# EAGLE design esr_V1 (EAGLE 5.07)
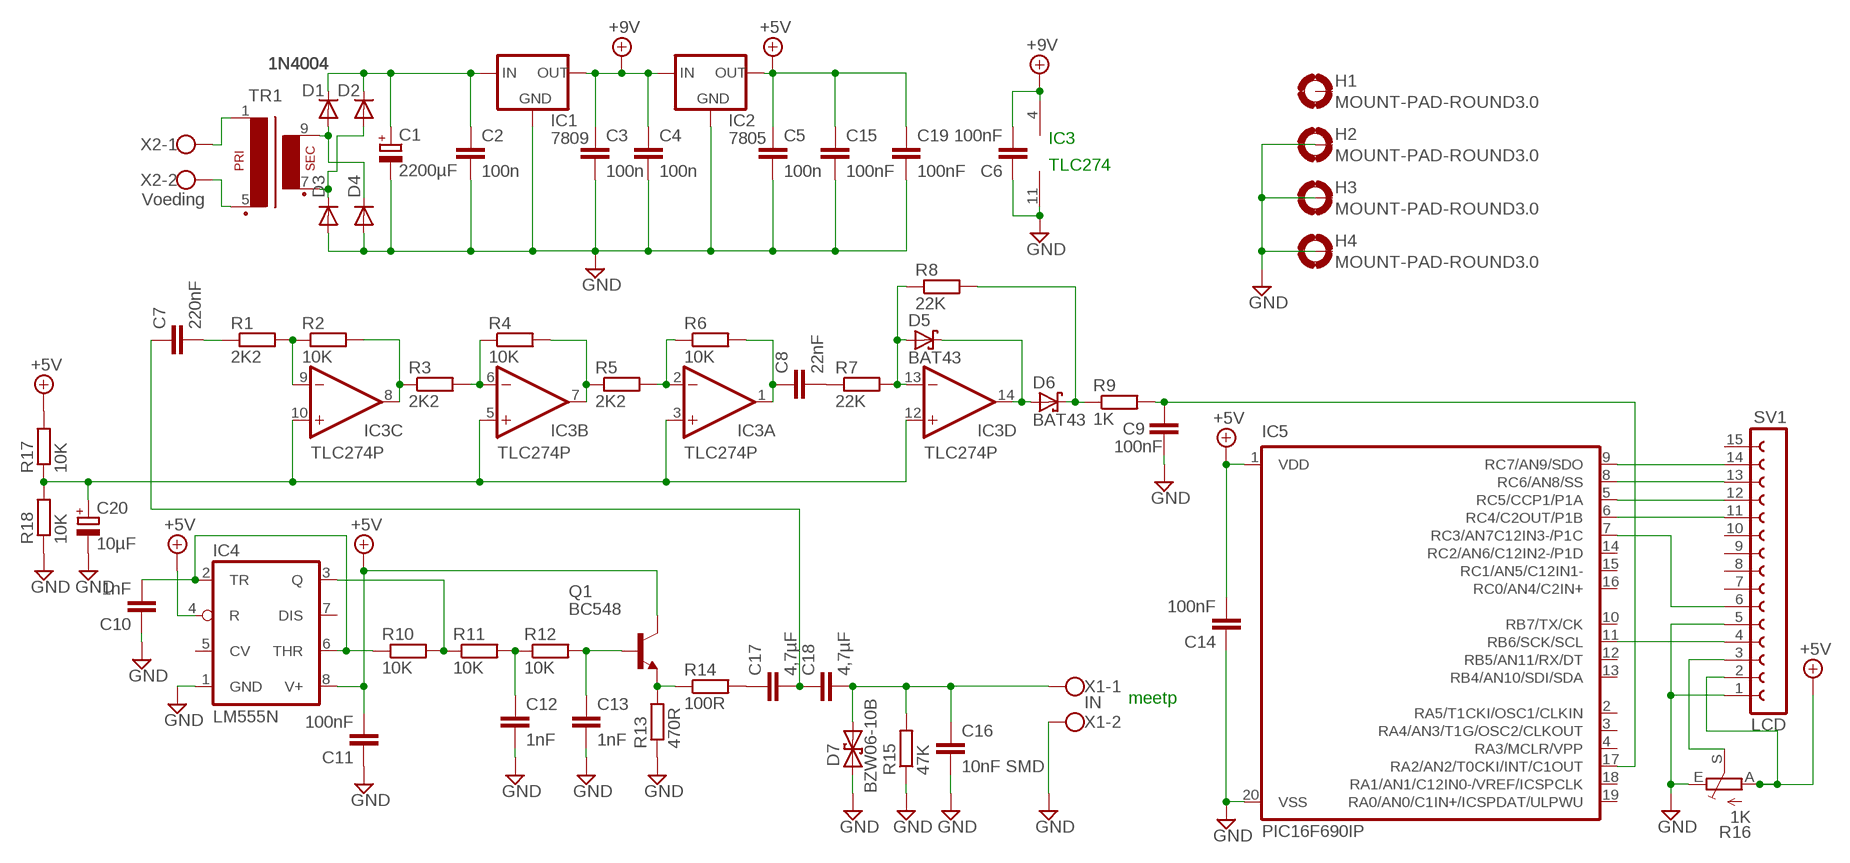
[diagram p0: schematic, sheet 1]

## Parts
C1  2200µF  CPOL-EUE7.5-18  [E7,5-18]
C2  100n  C-EU050-025X075  [C050-025X075]
C3  100n  C-EU050-025X075  [C050-025X075]
C4  100n  C-EU050-025X075  [C050-025X075]
C5  100n  C-EU050-025X075  [C050-025X075]
C6  100nF  C-EU050-025X075  [C050-025X075]
C7  220nF  C-EU050-025X075  [C050-025X075]
C8  22nF  C-EU050-025X075  [C050-025X075]
C9  100nF  C-EU050-025X075  [C050-025X075]
C10  1nF  C-EU050-025X075  [C050-025X075]
C11  100nF  C-EU050-025X075  [C050-025X075]
C12  1nF  C-EU050-025X075  [C050-025X075]
C13  1nF  C-EU050-025X075  [C050-025X075]
C14  100nF  C-EU050-025X075  [C050-025X075]
C15  100nF  C-EU050-025X075  [C050-025X075]
C16  10nF SMD  C-EU050-025X075  [C050-025X075]
C17  4,7µF  C-EU275-113X316  [C275-113X316]
C18  4,7µF  C-EU275-113X316  [C275-113X316]
C19  100nF  C-EU050-025X075  [C050-025X075]
C20  10µF  CPOL-EUE5-8.5  [E5-8,5]
D1  1N4004  [DO41-10]
D2  1N4004  [DO41-10]
D3  1N4004  [DO41-10]
D4  1N4004  [DO41-10]
D5  BAT43  BAT42  [DO35-10]
D6  BAT43  BAT42  [DO35-10]
D7  BZW06-10B  BZW04XXB  [F126Z12]
H1  MOUNT-PAD-ROUND3.0  [3,0-PAD]
H2  MOUNT-PAD-ROUND3.0  [3,0-PAD]
H3  MOUNT-PAD-ROUND3.0  [3,0-PAD]
H4  MOUNT-PAD-ROUND3.0  [3,0-PAD]
IC1  7809  78XXS  [78XXS]
IC2  7805  78XXS  [78XXS]
IC3  TLC274P  [DIL14]
IC4  LM555N  [DIL08]
IC5  PIC16F690IP  [DIL20]
Q1  BC548  [TO92-EBC]
R1  2K2  R-EU_0204/7  [0204/7]
R2  10K  R-EU_0204/7  [0204/7]
R3  2K2  R-EU_0204/7  [0204/7]
R4  10K  R-EU_0204/7  [0204/7]
R5  2K2  R-EU_0204/7  [0204/7]
R6  10K  R-EU_0204/7  [0204/7]
R7  22K  R-EU_0204/7  [0204/7]
R8  22K  R-EU_0204/7  [0204/7]
R9  1K  R-EU_0204/7  [0204/7]
R10  10K  R-EU_0204/7  [0204/7]
R11  10K  R-EU_0204/7  [0204/7]
R12  10K  R-EU_0204/7  [0204/7]
R13  470R  R-EU_0204/7  [0204/7]
R14  100R  R-EU_0204/7  [0204/7]
R15  47K  R-EU_0204/7  [0204/7]
R16  1K  TRIM_EU-S63P  [S63P]
R17  10K  R-EU_0204/7  [0204/7]
R18  10K  R-EU_0204/7  [0204/7]
SV1  LCD  FE15-1  [FE15]
TR1  EI30-1  [EI30-1]
X1  IN  W237-102  [W237-102]
X2  Voeding  W237-2N  [W237-2N]

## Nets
+5V: C5.1 C11.2 C14.2 C15.1 C19.1 IC2.OUT IC4.4(R) IC4.8(V+) IC5.1(VDD) Q1.C R16.A R17.2 SV1.2
+9V: C3.1 C4.1 C6.2 IC1.OUT IC2.IN IC3.4(P:V+)
GND: C1.- C2.2 C3.2 C4.2 C5.2 C6.1 C9.1 C10.1 C11.1 C12.2 C13.2 C14.1 C15.2 C16.2 C19.2 C20.- D3.A D4.A D7.A H2.B3,0(MOUNT) H3.B3,0(MOUNT) H4.B3,0(MOUNT) IC1.GND IC2.GND IC3.11(P:V-) IC4.1(GND) IC5.20(VSS) R13.1 R15.1 R16.E R18.1 SV1.1 SV1.5 X1.2
N$1: TR1.5(P2) X2.2
N$2: TR1.1 X2.1
N$3: D1.A D4.C TR1.9(S4)
N$4: D2.A D3.C TR1.7(S3)
N$6: IC3.8(C:OUT) R2.2 R3.1
N$7: IC3.6(B:-IN) R3.2 R4.1
N$8: C7.2 R1.1
N$9: IC3.9(C:-IN) R1.2 R2.1
N$10: IC3.7(B:OUT) R4.2 R5.1
N$11: IC5.9(RC7/AN9/SDO) SV1.14
N$13: C8.2 R7.1
N$14: D5.A IC3.13(D:-IN) R7.2 R8.1
N$15: D5.C D6.A IC3.14(D:OUT)
N$16: D6.C R8.2 R9.1
N$17: C9.2 IC5.17(RA2/AN2/T0CKI/INT/C1OUT) R9.2
N$18: C10.2 IC4.2(TR) IC4.6(THR) R10.1
N$19: IC4.3(Q) R10.2 R11.1
N$20: C12.1 R11.2 R12.1
N$21: C13.1 Q1.B R12.2
N$22: Q1.E R13.2 R14.1
N$23: C17.1 R14.2
N$24: IC3.2(A:-IN) R5.2 R6.1
N$25: C7.1 C17.2 C18.1
N$26: C16.1 C18.2 D7.C R15.2 X1.1
N$27: IC5.8(RC6/AN8/SS) SV1.13
N$28: IC5.5(RC5/CCP1/P1A) SV1.12
N$29: IC5.6(RC4/C2OUT/P1B) SV1.11
N$30: IC5.11(RB6/SCK/SCL) SV1.4
N$31: IC5.7(RC3/AN7C12IN3-/P1C) SV1.6
N$32: C8.1 IC3.1(A:OUT) R6.2
N$35: C20.+ IC3.3(A:+IN) IC3.5(B:+IN) IC3.10(C:+IN) IC3.12(D:+IN) R17.1 R18.2
N$37: R16.S SV1.3
N$72: C1.+ C2.1 D1.C D2.C IC1.IN
Unconnected: H1.B3,0(MOUNT) IC4.5(CV) IC4.7(DIS) IC5.2(RA5/T1CKI/OSC1/CLKIN) IC5.3(RA4/AN3/T1G/OSC2/CLKOUT) IC5.4(RA3/MCLR/VPP) IC5.10(RB7/TX/CK) IC5.12(RB5/AN11/RX/DT) IC5.13(RB4/AN10/SDI/SDA) IC5.14(RC2/AN6/C12IN2-/P1D) IC5.15(RC1/AN5/C12IN1-) IC5.16(RC0/AN4/C2IN+) IC5.18(RA1/AN1/C12IN0-/VREF/ICSPCLK) IC5.19(RA0/AN0/C1IN+/ICSPDAT/ULPWU) SV1.7 SV1.8 SV1.9 SV1.10 SV1.15

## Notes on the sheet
- IC3
- TLC274
- meetp

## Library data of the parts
C1 C20 = rcl:CPOL-EU: POLARIZED CAPACITOR, European symbol
C2-C19 = rcl:C-EU: CAPACITOR, European symbol
D1-D4 = diode:1N4004: DIODE
D5 D6 = diode:BAT42: DIODE
D7 = diode:BZW04XXB: DIODE
H1-H4 = holes:MOUNT-PAD-ROUND: MOUNTING PAD, round
IC1 IC2 = v-reg:78XXS: VOLTAGE REGULATOR
IC3 = linear:TLC274: OP AMP
IC4 = linear:*555: TIMER
IC5 = microchip-5:PIC16F690*: MICROCONTROLLER PIC16F690 18 I/O One 16-bit timer Two 8-bit timer Two comparators Precision internal oscillator-software selectable 8 MHz - 32 KHz SSP w/ I2C Compatible Address mask option EUSART LIN 2.0 Compatible ECCP+ w/ PWM Steering 12 A/D Channels ULPW Enhanced Low Power Timer 1 Timer 1 Gate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
Q1 = transistor-npn:BC548*: NPN Transistor
R1-R15 R17 R18 = rcl:R-EU_: RESISTOR, European symbol
R16 = pot:TRIM_EU-: POTENTIOMETER
SV1 = con-lsta:FE15-1: FEMALE HEADER
TR1 = trafo:EI30-1: TRANSFORMER 1 primary winding, 1 secondary winding ERA
X1 = con-wago-500:W237-102: WAGO SCREW CLAMP
X2 = con-wago-508:W237-2N: WAGO SREW CLAMP

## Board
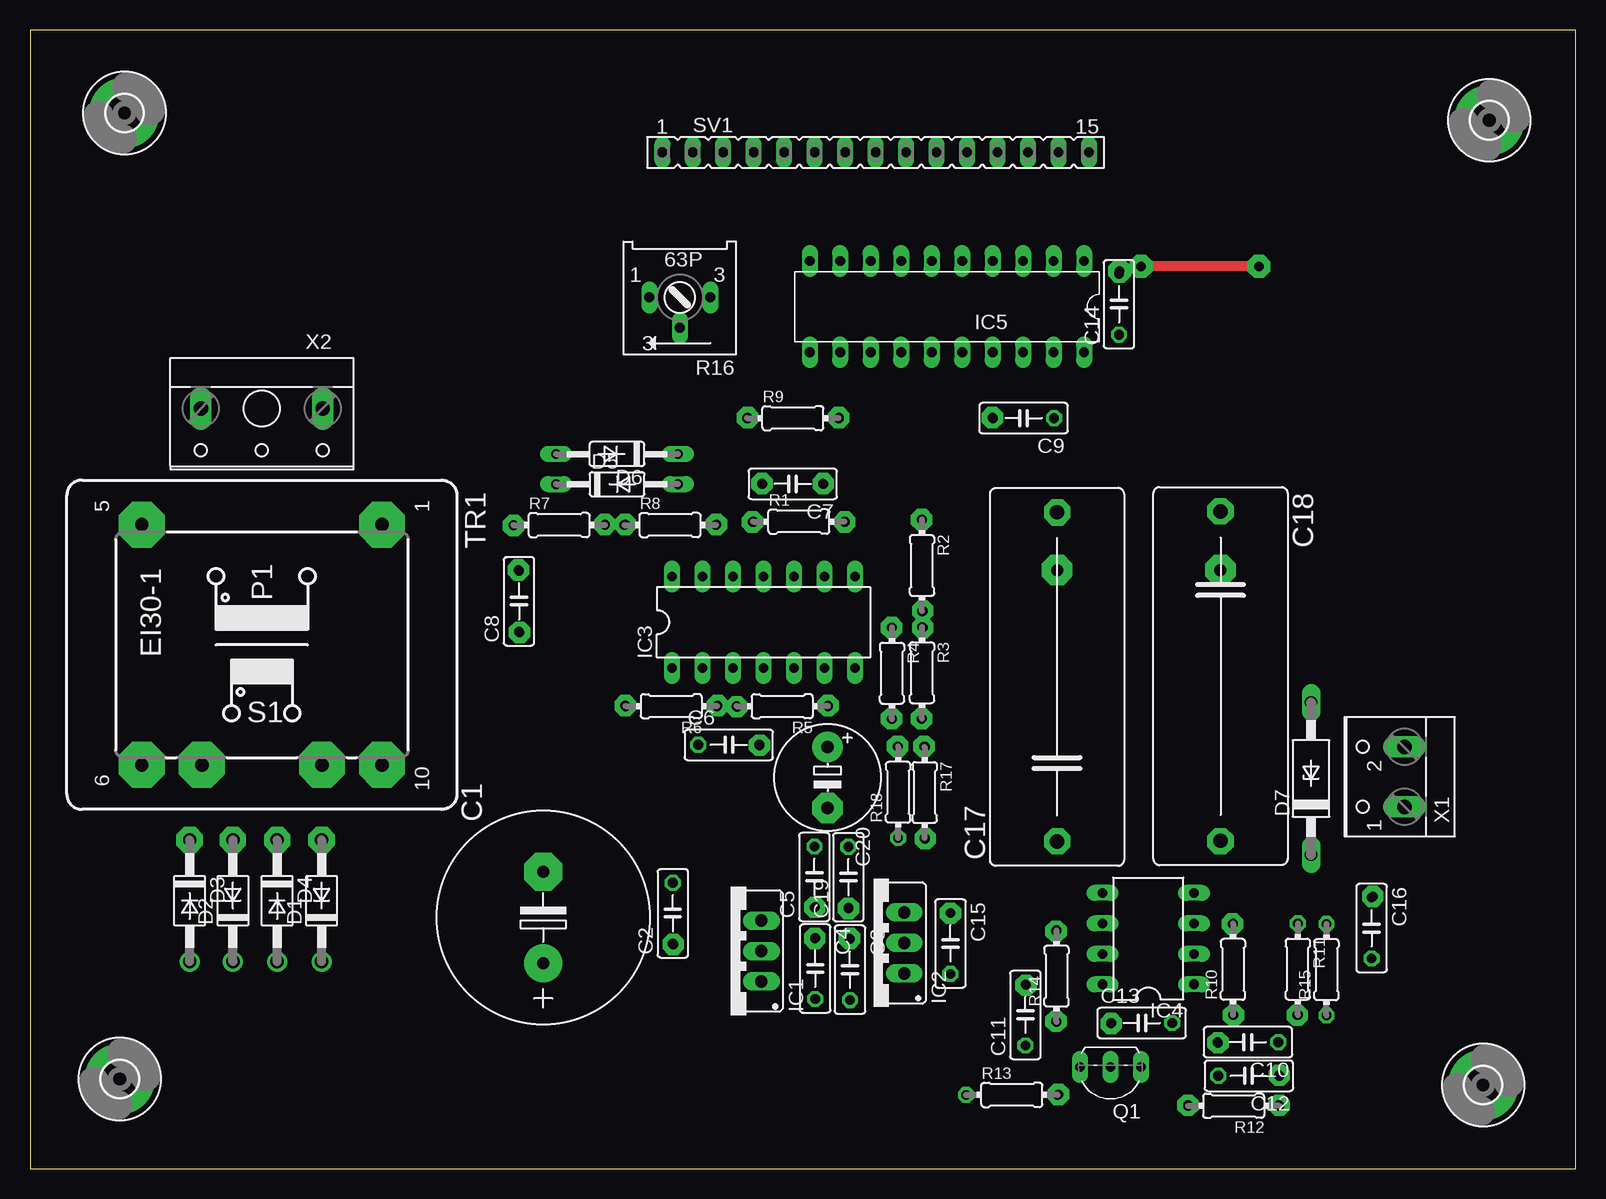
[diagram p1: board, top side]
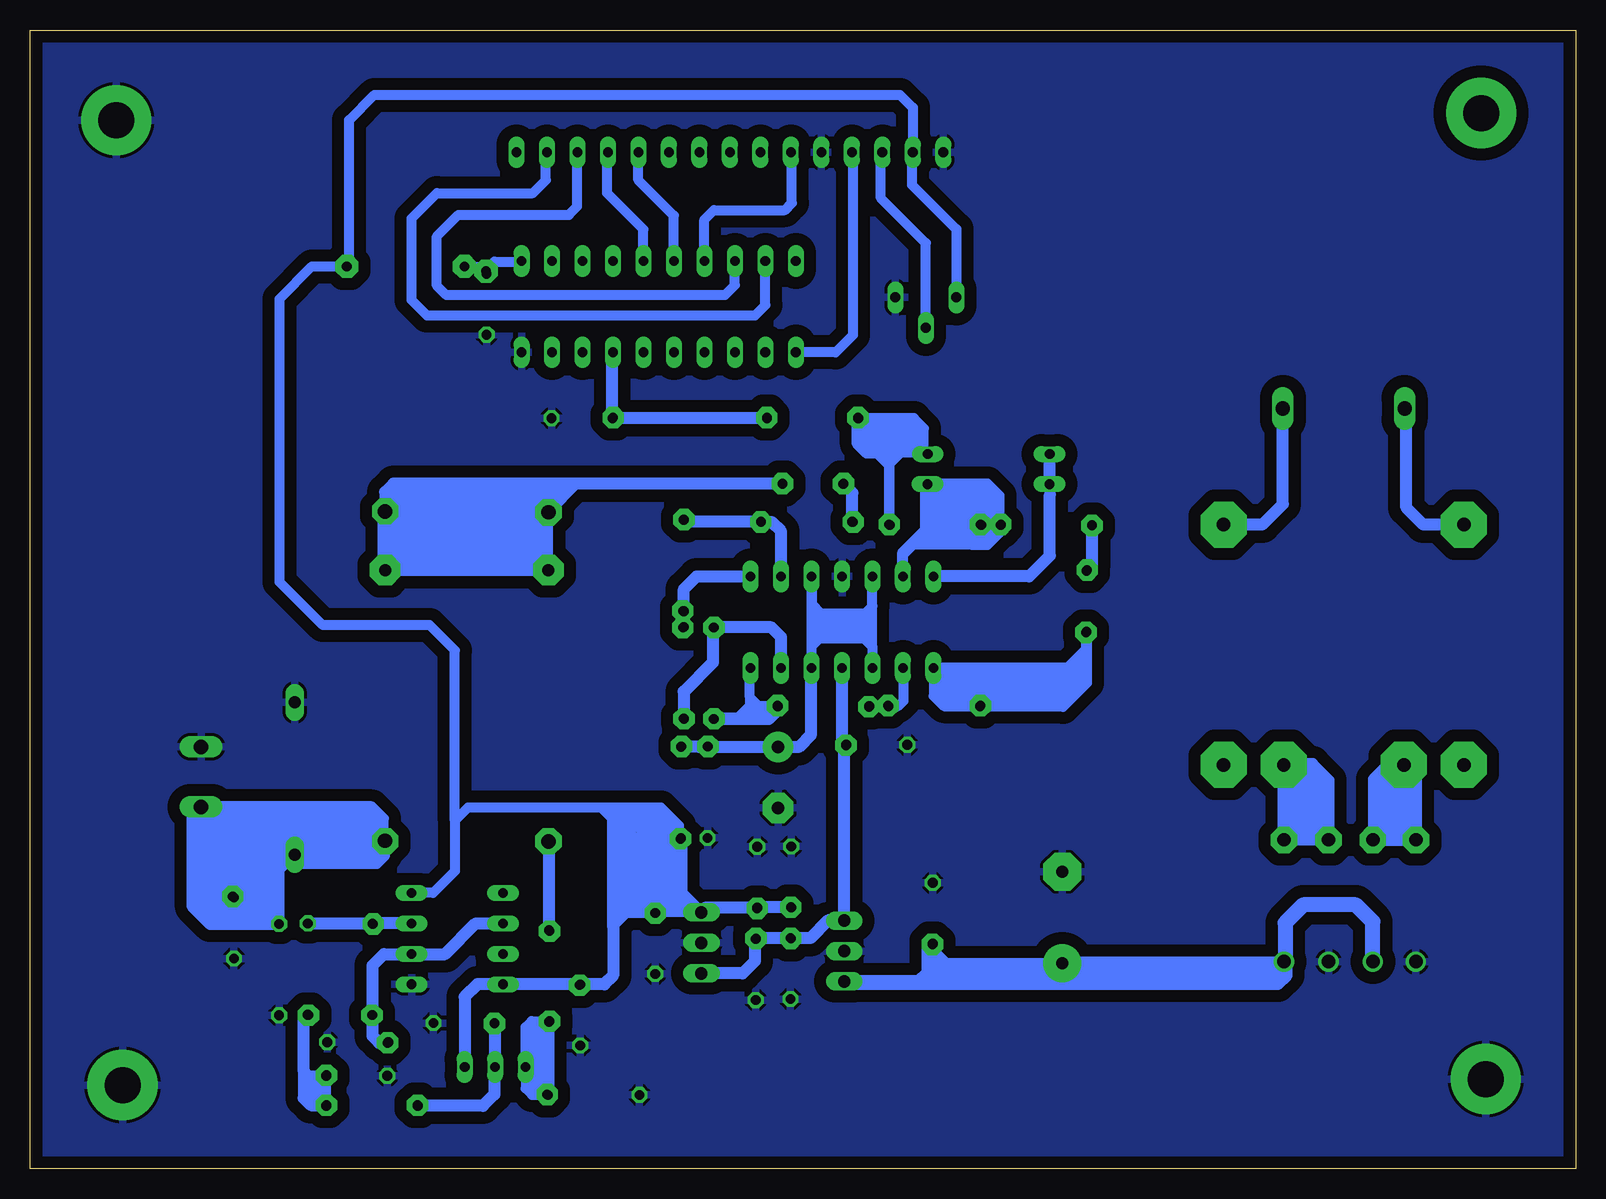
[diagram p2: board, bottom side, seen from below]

Size 128.8 x 94.9 mm. Coordinates in mm from the lower left corner, seen from the top.
Outline: 0,0 128.8,0 128.8,94.9 0,94.9 0,0
Copper layers (1*16): Top 0.035mm / dielectric 1.5mm / Bottom 0.035mm
Design rules "default": minimum track width 10mil, minimum drill 24mil, track to track 8mil, track to pad 8mil, pad to pad 8mil, via to via 8mil, smd to smd 8mil, copper to edge 40mil, drill to drill 8mil, minimum pad ring 10mil, minimum via ring 8mil, stop-mask expansion 4mil, vias tented up to drill 0mil, thermal gap 10mil

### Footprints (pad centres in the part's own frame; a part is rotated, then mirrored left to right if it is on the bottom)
E7,5-18 = drill 1.016 pad 3.15 round: + -3.81,0 | drill 1.016 pad 3.15 octagon: - 3.81,0
C050-025X075 = drill 0.813 octagon: 1 -2.54,0; 2 2.54,0
C275-113X316 = drill 1.194 octagon: 1 -13.716,0; 2 13.716,0
E5-8,5 = drill 1.016 pad 2.54 round: + -2.54,0 | drill 1.016 pad 2.54 octagon: - 2.54,0
DO41-10 = drill 1.118 round: A 5.08,0; C -5.08,0
DO35-10 = drill 0.813 long: A 5.08,0; C -5.08,0
F126Z12 = drill 1.016 long: A 6.35,0; C -6.35,0
3,0-PAD = drill 3 pad 5.842 round: B3,0 0,0
78XXS = drill 1.016 long: GND 0,-2.54; IN -2.54,-2.54; OUT 2.54,-2.54
DIL14 = drill 0.813 long: 1 -7.62,-3.81; 2 -5.08,-3.81; 3 -2.54,-3.81; 4 0,-3.81; 5 2.54,-3.81; 6 5.08,-3.81; 7 7.62,-3.81; 8 7.62,3.81; 9 5.08,3.81; 10 2.54,3.81; 11 0,3.81; 12 -2.54,3.81; 13 -5.08,3.81; 14 -7.62,3.81
DIL08 = drill 0.813 long: 1 -3.81,-3.81; 2 -1.27,-3.81; 3 1.27,-3.81; 4 3.81,-3.81; 5 3.81,3.81; 6 1.27,3.81; 7 -1.27,3.81; 8 -3.81,3.81
DIL20 = drill 0.813 long: 1 -11.43,-3.81; 2 -8.89,-3.81; 3 -6.35,-3.81; 4 -3.81,-3.81; 5 -1.27,-3.81; 6 1.27,-3.81; 7 3.81,-3.81; 8 6.35,-3.81; 9 8.89,-3.81; 10 11.43,-3.81; 11 11.43,3.81; 12 8.89,3.81; 13 6.35,3.81; 14 3.81,3.81; 15 1.27,3.81; 16 -1.27,3.81; 17 -3.81,3.81; 18 -6.35,3.81; 19 -8.89,3.81; 20 -11.43,3.81
TO92-EBC = drill 0.813 long: B 0,-1.27; C -2.54,-1.27; E 2.54,-1.27
0204/7 = drill 0.813 octagon: 1 -3.81,0; 2 3.81,0
S63P = drill 0.813 long: A 2.54,0; E -2.54,0; S 0,2.54
FE15 = drill 0.813 long: 1 -17.78,0; 2 -15.24,0; 3 -12.7,0; 4 -10.16,0; 5 -7.62,0; 6 -5.08,0; 7 -2.54,0; 8 0,0; 9 2.54,0; 10 5.08,0; 11 7.62,0; 12 10.16,0; 13 12.7,0; 14 15.24,0; 15 17.78,0
EI30-1 = drill 1.118 pad 3.81 octagon: 1 -10.008,10.008; 5 -10.008,-10.008; 6 10.008,-10.008; 7 10.008,-5.004; 9 10.008,5.004; 10 10.008,10.008
W237-102 = drill 1.194 long: 1 -2.5,-1.27; 2 2.5,-1.27
W237-2N = drill 1.194 long: 1 -5.08,-0.635; 2 5.08,-0.635

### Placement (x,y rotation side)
C1  42.77,20.94 90 top
C2  53.57,21.29 90 top
C3  68.33,16.6 270 top
C4  65.43,16.69 270 top
C5  65.37,24.32 90 top
C6  58.23,35.33 0 top
C7  63.56,57.07 180 top
C8  40.75,47.29 90 top
C9  82.8,62.55 180 top
C10  101.49,10.55 180 top
C11  82.95,12.82 90 top
C12  101.57,7.75 180 top
C13  92.64,12.15 0 top
C14  90.75,72.05 90 top
C15  76.7,18.78 270 top
C16  111.8,20.06 270 top
C17  85.59,40.99 90 top
C18  99.21,41.06 270 top
C19  68.2,24.3 90 top
C20  66.46,32.61 270 top
D1  24.3,22.34 90 top
D2  16.9,22.34 90 top
D3  13.31,22.34 270 top
D4  20.59,22.34 270 top
D5  48.92,57.05 0 top
D6  48.91,59.56 180 top
D7  106.75,32.52 90 top
H1  7.87,87.98 0 top
H2  7.48,7.48 0 top
H3  121.09,6.98 0 top
H4  121.6,87.38 0 top
IC1  58.41,18.15 90 top
IC2  70.31,18.82 90 top
IC3  61.13,45.55 0 top
IC4  93.19,19.18 90 top
IC5  76.41,71.85 180 top
Q1  90.04,7.22 180 top
R1  64.08,53.93 0 top
R2  74.33,50.28 270 top
R3  74.33,41.34 270 top
R4  71.83,41.3 270 top
R5  62.68,38.55 180 top
R6  53.44,38.55 180 top
R7  44.1,53.65 0 top
R8  53.34,53.65 0 top
R9  63.58,62.55 0 top
R10  100.25,16.62 90 top
R11  105.65,16.64 270 top
R12  100.3,5.25 180 top
R13  81.82,6.16 0 top
R14  85.54,16.06 90 top
R15  108.04,16.6 90 top
R16  54.15,72.62 180 top
R17  74.56,31.36 270 top
R18  72.34,31.38 90 top
SV1  70.47,84.71 0 top
TR1  19.32,43.67 270 top
X1  113.27,32.66 90 top
X2  19.32,62.72 180 top

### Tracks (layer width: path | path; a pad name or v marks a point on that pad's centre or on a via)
+5V  (via drill 0.6, 0.8 pad 1.78, 0.8 pad 1.93)
  Top 0.813: v102.5,75.2 v102.4,75.2 v92.7,75.2
  Bottom 0.813: 68.18,21.78 C19.1 | 72.45,21.76 IC2.OUT 76.26,21.36 | IC4.8 89.41,15.4 | 76.26,21.36 C15.1 76.32,21.3 v76.7,21.3 79.1,21.3 80.2,20.2 | 76.26,21.36 76.26,26.75 R17.2 74.7,27.69 74.7,28.6 76.2,30.1 92.3,30.1 93.4,29 | C11.2 | IC4.4 95.21,22.99 93.4,24.8 93.4,29 | 93.4,29 93.4,43.2 95.5,45.3 104.4,45.3 108,48.9 108,72.5 105.3,75.2 v102.5,75.2 102.2,75.5 102.2,87.4 100.1,89.5 56.3,89.5 55.23,88.43 SV1.2 55.3,84.64 55.3,82 51.61,78.31 R16.A | IC5.1 87.91,75.59 90.11,75.59 90.5,75.2 90.5,74.9 | v92.7,75.2 v92.69,75.19 90.79,75.19 90.5,74.9 | 90.5,74.9 90.5,74.64 C14.2 | 80.2,29.1 81.1,30
  Bottom 1.016: C5.1 68.18,21.78 | C19.1 72.45,21.76 | Q1.C 92.58,14.32 91.5,15.4 89.41,15.4 | C11.2 80.94,15.36 80.2,16.1 80.2,20.2 80.2,29.1 | C11.2 IC4.8
+9V  (via drill 0.8 pad 1.78)
  Bottom 0.813: IC1.OUT | 68.24,19.23 C3.1 68.4,19.07 | 60.96,35.14 v60.8,35.3 C6.2
  Bottom 1.016: 68.24,19.23 C4.1 63.77,19.23 62.3,20.7 IC1.OUT 60.96,35.14 | IC2.IN 69.42,16.28 68.4,17.3 68.4,19.07 | IC3.4 61.13,35.69 C6.2
GND
  pour Bottom (isolate 1.016): -0.5,95.4 129,95.3 129,-0.4 -0.4,-0.4 -0.4,95.3
N$1
  Bottom 1.016: TR1.5 12.68,53.68 14.1,55.1 14.1,63.4 14.6,63.9 14.6,63.71 X2.2
N$2
  Bottom 1.016: TR1.1 26.12,53.68 24.4,55.4 X2.1
N$3
  Bottom 0.813: 24.3,33.64 TR1.9
  Bottom 1.016: D4.C D1.A 24.3,33.64
N$4
  Bottom 0.813: D3.C 14.32,28.43 TR1.7 14.35,33.7 15.7,33.7 16.9,32.5 D2.A
N$5  (via drill 0.8 pad 1.78)
  other vias: 47.9,53.7
N$6
  Bottom 0.813: 74.3,46.5 R2.2 R3.1
  Bottom 1.016: IC3.8 73.24,49.36 74.3,48.3 74.3,46.5
N$7
  Bottom 0.813: IC3.6 | R4.1 71.9,45.04
  Bottom 1.016: R4.1 67.01,45.11 66.2,44.3 IC3.6 | R3.2 74.33,39.77 71.9,42.2 71.9,45.04
N$8
  Bottom 1.016: R1.1 60.27,56.32 C7.2
N$9
  Bottom 0.813: 67.86,53.9 R1.2 | 74.17,53.93 R2.1
  Bottom 1.016: IC3.9 66.21,53.11 67,53.9 67.86,53.9 | R1.2 74.17,53.93
N$10
  Bottom 0.813: R5.1 68.05,38.55 68.8,39.3 | IC3.7 68.8,41.49 68.8,40.9 68.8,39.3 | R4.2 69.51,37.49 68.8,38.2 68.8,38.6 | 68.8,39.3 68.8,38.6 | 71.6,37.6 69.8,37.6 68.8,38.6
N$11
  Bottom 0.813: IC5.9 67.52,71.98 68.4,71.1 95.7,71.1 97,72.4 97,79.2 94.9,81.3 86.9,81.3 85.8,82.4 85.8,84.62 SV1.14
N$12
  Bottom 0.813: 48,53.9 48,56.1 49,57.1 53.5,57.1
N$13
  Bottom 1.016: R7.1 40.29,50.29 C8.2
N$14
  Bottom 0.813: IC3.13 56.05,51.15 55.2,52 50.3,52 | 49.6,52.7 49.5,52.8 49.5,53.62 R8.1 48.6,53.65 | 49.6,52.7 50.3,52 | 48.6,53.65 R7.2 | D5.A 49.55,57.05 48.8,56.3 48.8,53.85 48.6,53.65 | 50.3,52 49,52 47.9,53.1 47.9,53.3 48,53.4 | 49.6,52.7 48.7,52.7 48.4,53 48.8,53 49,53.2
N$15
  Bottom 0.813: 43.8,56.19 D5.C | D6.A
  Bottom 1.016: IC3.14 45.54,49.36 43.8,51.1 43.8,56.19 | D5.C D6.A
N$16
  Bottom 0.813: R8.2 57.15,58.75 56.2,59.7 54.13,59.7 D6.C 54.3,59.87 54.3,61.7 55.15,62.55 R9.1
N$17
  Bottom 0.813: 80.26,68 IC5.17
  Bottom 1.016: R9.2 C9.2 80.26,68
N$18  (via drill 0.8 pad 1.78)
  Bottom 0.813: IC4.2 | R10.1 100.29,12.85 | C10.2 v99,10.5
  Bottom 1.016: IC4.2 99.3,17.9 100.25,16.95 R10.1 100.25,11.05 99.7,10.5 v99,10.5 | IC4.6 91.65,20.45 94.2,17.9 IC4.2
N$19
  Bottom 0.813: 100.23,20.45 R10.2 | 105.63,20.43 R11.1
  Bottom 1.016: IC4.3 100.23,20.45 | R10.2 105.63,20.43
N$20  (via drill 0.8 pad 1.78)
  Bottom 0.813: R12.1 C12.1 105.55,7.75 106,8.2 | 106,12.48 R11.2
  Bottom 1.016: 106,12.48 106,8.2 106,5.9 105.4,5.3 v104.1,5.3
N$21
  Bottom 0.813: 90.04,12.09 C13.1 | Q1.B 90.1,8.43
  Bottom 1.016: Q1.B 90.04,12.09 | R12.2 91.05,5.25 90.1,6.2 90.1,8.43
N$22
  Bottom 0.813: 85.5,9.2 86.21,8.49 Q1.E 87.5,6.7 86.96,6.16 R13.2 | 85.5,9.2 85.5,10.9 85.5,12.21 R14.1 | 85.5,6.5 85.5,9.2
N$23
  Bottom 0.813: 85.54,27.22 C17.1
  Bottom 1.016: R14.2 85.54,27.22
N$24
  Bottom 0.813: R5.2 R6.1 56.45,38.55 56,39 56,41.69 IC3.2
N$25
  Bottom 0.813: C7.1 83.23,57.07 C17.2 85.66,54.78 C18.1
N$26
  Bottom 0.813: C18.2 105.58,27.34 D7.C | R15.2 108.04,24.88 D7.C | C16.1 111.8,25.3 110.6,26.5 107.08,26.5 D7.C | X1.1 107.86,30.16 106.7,29 106.7,26.8 106.8,26.7 106.8,26.22 D7.C
N$27
  Bottom 0.813: IC5.8 70.06,73.64 70.9,72.8 94.1,72.8 94.9,73.6 94.9,77.7 93.1,79.5 83.9,79.5 83.2,80.2 83.2,84.68 SV1.13
N$28
  Bottom 0.813: IC5.5 77.68,78.28 80.7,81.3 80.7,84.64 SV1.12
N$29
  Bottom 0.813: IC5.6 75.14,79.44 78.1,82.4 SV1.11
N$30
  Bottom 0.813: IC5.11 61.66,68.04 60.2,69.5 60.2,84.6 SV1.4
N$31
  Bottom 0.813: IC5.7 72.6,79.1 71.8,79.9 65.9,79.9 65.3,80.5 65.3,84.62 SV1.6
N$32  (via drill 0.8 pad 1.78)
  Bottom 0.813: 49.6,38.5 42.7,38.5 40.7,40.5 40.7,44.4 40.8,44.5 | 40.8,44.5 40.8,43.3 42.36,41.74 IC3.1 53.5,39.4 52.65,38.55 R6.2 | 40.8,44.5 v40.8,44.7 C8.1
N$33
  Bottom 0.813: 41,42.5 42.3,41.2 52.7,41.2 53,40.9 53,39.9 52.4,39.3 42.9,39.3 41.2,41 41.2,41.4 41.8,41.4 43.4,39.8 51.9,39.8 52.6,40.5 43.6,40.5 43.1,41
N$34
  Bottom 0.813: 71.5,37.4 67.2,37.4 66.5,38.1 66.5,38.5
N$35
  Bottom 0.813: 63.67,43.53 IC3.5 63.7,41.57 | 63.67,43.53 63,44.2 59.3,44.2 58.6,43.5 | 58.6,43.5 IC3.3 | 63.67,43.53 IC3.10 63.67,47.07 62.9,46.3 59.2,46.3 58.6,46.9 IC3.12 | 73,35.15 R18.2 73.06,35.17 | 58.6,43.5 58.6,48.9 58.7,49
  Bottom 1.016: 63.7,41.57 63.7,36.2 64.75,35.15 C20.+ 73,35.15 | 73.06,35.17 R17.1
N$36
  Bottom 0.813: 67,38.1 68.1,38.1 68.3,37.9
N$37
  Bottom 0.813: R16.S 54.15,77.15 57.9,80.9 57.9,84.58 SV1.3
N$38
  Bottom 0.813: 54.2,57.1 54.2,53.3 56.1,51.4 56.1,49.5
N$39
  Bottom 0.813: 54.6,52.6 50.6,52.6 50.1,53.1 50.1,54.1 49.5,54.7 49.5,55.2 49.4,55.3 | 49.4,55 49.4,55.3 | 49.4,55 49.4,54.6 | 49.4,55.3 49.4,56 50.1,56.7 53.7,56.7 53.7,53.2 53.9,53 51,53 50.7,53.3 50.7,53.9 | 50.7,53.9 50.7,55.8 51,56.1 50.5,56.1 50.4,56.2 50.3,56.2 49.9,55.8 49.9,55.1 50.3,54.7 | 50.3,54.7 50.3,54.6 | 50.3,54.7 50.3,55.2 51.2,56.1 53.3,56.1 53.3,54.9 53.2,54.8 53.2,53.7 53,53.5 51.6,53.5 51.4,53.7 50.9,53.7 50.7,53.9 | 50.7,53.9 52.8,53.9 52.9,53.8 52.9,54 53.1,54.2 51.5,54.2 51.2,54.5 52.3,54.5 52.6,54.8 50.8,54.8 50.4,55.2 53.5,55.2 53.6,55.1 51.2,55.1 50.8,55.5 52.8,55.5 52.9,55.6 50,55.6 49.4,55
N$40
  Bottom 0.813: 59.1,46.1 62.7,46.1 63.3,45.5 63.3,44.9 63.1,44.7 59,44.7 59,45.1 59.2,45.3 62.5,45.3 62.6,45.2 62,45.2 61.8,45.4 61.7,45.4 61.7,45.5 62.1,45.5 62.2,45.6
N$45
  Bottom 0.813: 85.8,6.6 86.1,6.9 86.9,6.9 87,7 87,7.7 86.8,7.9 86.6,7.9 86.5,8 86,8 86.2,7.8 86.2,7.2 86.4,7.4 86.4,7.5
N$46
  Bottom 0.813: 104.7,5.6 104.7,7.1 105.4,7.1 105.5,7.2 105.5,6.5 105.1,6.1 105.1,6.8
N$47
  Bottom 0.813: 108.2,20.3 111.2,20.3 | 111.2,20.3 111.9,21 111.9,22.3 111.8,22.4 | 111.2,20.3 113.8,20.3 115.3,21.8 115.3,29.3 114.7,29.9
N$48
  Bottom 0.813: 112.1,22.4 114.3,22.4 115.1,23.2 115.1,29.2 114.4,29.9
N$49
  Bottom 0.813: 106.6,25.4 99.9,25.4 99.2,26.1 99.2,26.7 99.3,26.8
N$50
  Bottom 0.813: 99.6,26.8 105.5,26.8 106.6,25.7 100.2,25.7 99.7,26.2 105.4,26.2 105.6,26
N$51
  Bottom 0.813: 114.4,30.2 100.3,30.2 99.3,29.2 99.3,27.2
N$52
  Bottom 0.813: 99.9,27.5 99.9,29 100.5,29.6 113.8,29.6 114.5,28.9 100.6,28.9 100.4,28.7 100.4,28.5 100.3,28.4 114.7,28.4 114.8,28.3 114.8,27.9 114.7,27.8 100.1,27.8 100,27.9 105.5,27.9 106.4,27 114.7,27 114.7,26.9 114.6,26.8 114.6,23.5 114.2,23.1 112.5,23.1 112.3,22.9 112.3,23.7 | 112.3,23.7 112.3,24.9 112,25.2 112,25.4 110.9,26.5 113.5,26.5 113.7,26.3 114,26.3 114.1,26.4 114.1,25.2 | 114.1,25.2 114.1,24.1 114,24 114,23.8 112.4,23.8 112.3,23.7 | 112.3,23.7 112.7,23.7 | 112.7,23.7 113,23.7 113.9,24.6 112.9,24.6 112.8,24.7 113.6,24.7 114.1,25.2 | 114.1,25.2 112.7,25.2 112.5,25.4 113.7,25.4 113.9,25.6 112,25.6 111.6,26 113.1,26 113.1,24.1 112.7,23.7
N$53
  Bottom 0.813: 108.3,20.6 110.7,20.6 111.5,21.4 111.5,24.7 110.6,25.6 107.8,25.6 107.7,25.7 107.7,25.9 110.4,25.9
N$54
  Bottom 0.813: 108.6,20.9 108.6,25.1 110.2,25.1 111,24.3 111,22 110.3,21.3 109.2,21.3 109.2,24.6 109.3,24.7 109.8,24.7 110.1,24.4 110.1,21.9 110,21.8 109.7,21.8 109.6,21.9 109.6,24.2 109.7,24.3 110.4,24.3 110.5,24.4 110.5,22.3 110.3,22.1
N$55
  Bottom 0.813: 111.8,21.4 114.3,21.4 114.9,22 112.6,22 112.5,22.1 112.4,22.1 111.8,21.5 111.8,21.2 112.1,20.9 113.4,20.9 113.7,21.2
N$56
  Bottom 0.813: 57.2,54.1 57.2,58.6 58.2,59.6 59.1,59.6 59.9,60.4 59.9,62.1 59.7,62.3
N$57
  Bottom 0.813: 54.8,61.9 59.4,61.9 59.7,61.6 59.7,61 59.4,60.7 54.8,60.7 54.5,61 54.7,61.2 59.1,61.2 59.2,61.1 59.2,60.3 59.3,60.2 55.1,60.2 | 54.7,60.2 55.1,60.2 | 55.1,60.2 55.5,59.8 57.2,59.8 57.4,59.6 57.6,59.6
N$58
  Bottom 1.016: 66.2,57.1 98.5,57.1 99.2,56.4 99.2,55
N$59
  Bottom 0.813: 84.3,56.7 98,56.7 98.8,55.9 98.8,55.5 85.5,55.5 84.8,56.2 97.6,56.2 98.2,55.6
N$62
  Bottom 0.813: 74.4,27.5 74.4,23 73.1,21.7 75.5,21.7 75.7,21.9 75.7,26.3 75.6,26.4 75.4,26.4 75,26.8 75,22.4 75.1,22.3 74.1,22.3 74,22.2
N$63
  Bottom 0.813: 79.7,21.4 79.7,29.5 79.9,29.7 76.5,29.7 75.5,28.7 75.5,28.5 75.2,28.2 75.2,27.8 75.3,27.7 75.8,27.7 76.6,26.9 76.6,22.4 76.9,22.1 79,22.1 79.2,21.9 79.2,28.9 78.9,29.2 76.7,29.2 75.8,28.3 75.9,28.3 76.6,27.6 76.6,28.1 77,28.5 78.6,28.5 78.7,28.6 78.7,22.6 78.2,22.6 | 78.2,22.6 77.4,22.6 77.3,22.7 77.3,27.6 77,27.9 77.9,27.9 77.9,22.9 78.2,22.6 | 78.2,22.6 78.2,25.3 76.9,26.6 76.9,27.1 76.8,27.2
N$64  (via drill 0.8 pad 1.93)
  other vias: 92.6,75.2
N$65  (via drill 0.8 pad 1.93)
  other vias: 90.8,74.8
N$66  (via drill 1 pad 2.18)
  other vias: 85.6,54.7
N$67  (via drill 1 pad 2.18)
  other vias: 99.2,54.8
N$68  (via drill 1 pad 2.18)
  other vias: 99.2,27.3
N$69  (via drill 1 pad 2.18)
  other vias: 85.6,27.3
N$70
  Bottom 0.813: 56.2,15.6 25.1,15.6 24.3,16.4 24.3,16.9
N$71
  Bottom 0.813: 24.7,16.9 53,16.9 53.6,16.3 25.2,16.3 24.9,16.6
N$72
  Bottom 0.813: 60.8,15.7 54.8,15.7 54.1,16.4 54.1,18.2 53.8,18.5 | D1.C 42.64,17.26 C1.+ 52.93,17.13 53.8,18 | 53.8,18 53.8,18.5 | 53.8,18.5 53.8,18.52 C2.1 | IC1.IN 54.59,15.61 53.8,16.4 53.8,18
  Bottom 1.27: D2.C 16.9,20.6 18.3,22 22.7,22 24.2,20.5 24.2,17.36 D1.C
N$73
  Bottom 0.813: 52.5,16.7 52.5,17.2 53.5,18.2
N$74  (via drill 0.8 pad 1.78)
  other vias: 58.9,38.5
N$75  (via drill 0.8 pad 1.78)
  other vias: 57.3,38.6
N$76  (via drill 0.8 pad 1.78)
  other vias: 66.5,38.6
N$77  (via drill 0.8 pad 1.78)
  other vias: 49.6,38.6
N$78  (via drill 0.8 pad 1.78)
  other vias: 72.3,35.2
N$79  (via drill 0.8 pad 1.78)
  other vias: 74.5,35.2
N$80  (via drill 0.8 pad 1.78)
  other vias: 74.3,37.5
N$81  (via drill 0.8 pad 1.78)
  other vias: 71.8,37.5
N$82  (via drill 0.8 pad 1.78)
  other vias: 74.6,27.5
N$83  (via drill 0.8 pad 1.78)
  other vias: 68.2,21.7
N$84  (via drill 0.8 pad 1.78)
  other vias: 65.4,21.8
N$85  (via drill 0.8 pad 1.78)
  other vias: 68.3,19.2
N$86  (via drill 0.8 pad 1.78)
  other vias: 65.4,19.2
N$87
  Bottom 0.813: 87.5,8.5 87.5,11.8 87,12.3 85.7,12.3
N$88
  Bottom 0.813: 86.8,8.6 86.8,11.6 86.1,11.6 85.9,11.8 85.9,9.2 86.3,8.8 86.3,11 86.2,11.1
N$89  (via drill 0.8 pad 1.78)
  other vias: 90.1,12.1
N$90  (via drill 0.8 pad 1.78)
  other vias: 49.6,53.7
N$91  (via drill 0.8 pad 1.78)
  other vias: 57.2,53.7
N$92  (via drill 0.8 pad 1.78)
  other vias: 60.2,53.9
N$93  (via drill 0.8 pad 1.78)
  other vias: 67.9,53.9
N$94  (via drill 0.8 pad 1.78)
  other vias: 66.1,57.1
N$95  (via drill 0.8 pad 1.78)
  other vias: 61,57.1
N$96  (via drill 0.8 pad 1.78)
  other vias: 59.8,62.6
N$97  (via drill 0.8 pad 1.78)
  other vias: 67.4,62.6
N$98  (via drill 0.8 pad 1.78)
  other vias: 74.3,54.1
N$99  (via drill 0.8 pad 1.78)
  other vias: 74.4,46.5
N$100  (via drill 0.8 pad 1.78)
  other vias: 74.4,45.1
N$101  (via drill 0.8 pad 1.78)
  other vias: 71.8,45.1
N$102  (via drill 0.8 pad 1.78)
  other vias: 80.2,62.6
N$103  (via drill 0.8 pad 1.78)
  other vias: 53.6,18.7
N$104  (via drill 0.8 pad 1.78)
  other vias: 85.5,19.8
N$105  (via drill 0.8 pad 1.78)
  other vias: 85.5,12.3
N$106  (via drill 0.8 pad 1.78)
  other vias: 83,15.3
N$107  (via drill 0.8 pad 1.78)
  other vias: 85.7,6.2
N$108  (via drill 0.8 pad 1.78)
  other vias: 96.5,5.3
N$109  (via drill 0.8 pad 1.78)
  other vias: 104.1,7.8
N$110  (via drill 0.8 pad 1.78)
  other vias: 100.3,12.8
N$111  (via drill 0.8 pad 1.78)
  other vias: 105.6,12.8
N$112  (via drill 0.8 pad 1.78)
  other vias: 100.2,20.4
N$113  (via drill 0.8 pad 1.78)
  other vias: 111.9,22.7
N$114  (via drill 0.8 pad 1.78)
  other vias: 40.3,53.6
N$115  (via drill 0.8 pad 1.78)
  other vias: 40.7,49.9
N$116  (via drill 1 pad 2.18)
  other vias: 24.3,27.4
N$117  (via drill 1 pad 2.18)
  other vias: 20.6,27.4
N$118  (via drill 1 pad 2.18)
  other vias: 16.9,27.4
N$119  (via drill 1 pad 2.18)
  other vias: 13.3,27.4
N$120  (via drill 1 pad 2.54)
  other vias: 85.6,49.9
N$121  (via drill 1 pad 2.54)
  other vias: 99.2,49.9
N$122
  Bottom 1.016: 85.6,49.8 85.7,49.8 85.7,49.9 | 85.7,50.1 85.7,54.6 | 85.7,49.9 99.3,49.9 | 85.7,50.1 85.7,49.9 | 85.7,50.1 86.3,50.1 86.3,50.8 98.8,50.8 98.8,51.6 86.2,51.6 86.2,51.3 86.4,51.3 86.4,52.3 98.5,52.3 98.5,53 86.3,53 86.3,53.1 86.4,53.1 86.4,53.6 98.7,53.6 98.7,53.2 98.2,53.2 98.2,54.2 86.6,54.2 86.6,54.1
N$123
  Bottom 1.016: 99.2,50 99.3,50 99.3,54.7
N$124
  Bottom 0.813: 61.2,15.3 24.8,15.3 24,16.1 24,16.8
N$125
  Bottom 0.813: 20.5,27.4 20.5,32.4 21.9,33.8 24.1,33.8
N$126
  Bottom 0.813: 13.1,27.3 16.6,27.3 16.8,27.5
N$127
  Bottom 0.813: 16.4,27.9 16.4,32.2 15.5,33.1 15.5,32.2 14.9,31.6 14.9,28.5 14.3,27.9 15.7,27.9 15.7,31.8 | 15.7,31.8 16,32.1 | 15.7,31.8 15.5,31.6
N$128
  Bottom 0.813: 15.2,28.2 15.2,28.3 15.3,28.4 14.3,28.4 13.5,27.6 13.2,27.6 13.2,32.8 13.7,33.3
N$129
  Bottom 0.813: 13.7,28.4 13.7,32.8 14.2,33.3
N$130
  Bottom 0.813: 20.8,28.4 20.8,31.6 22.7,33.5 23,33.5 23.9,32.6 23.9,28.6 23.5,28.2 21.6,28.2 21.4,28.4 21.4,31.3 23,32.9 23,32.6 23.6,32 23.6,29.3 23.1,28.8 22,28.8 21.9,28.7 21.9,30.8 23.2,32.1 23.2,30 22.6,29.4 22.5,29.4 22.3,29.6 22.3,30.5 22.8,31 22.8,30.4 22.6,30.2 22.6,30.1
